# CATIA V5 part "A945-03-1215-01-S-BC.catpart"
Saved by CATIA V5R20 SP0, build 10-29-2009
Part number: A945-03-1215-01-S-BC
Source: Unknown
Property "ARTICLENO": "A945-03-1215-01-S-BC"
Property "B": "125.000"
Property "BOMINFO": "A945-03-1215-01-S-BC"
Property "CODE": "A945-03-1215-01-S-BC"
Property "D1": "26.000"
Property "D2": "17.500"
Property "D5": "20.000"
Property "D6": "16.000"
Property "H": "57.000"
Property "H1": "44.000"
Property "H2": "60.000"
Property "H3": "28.000"
Property "L1": "150.000"
Property "L2": "25.000"
Property "L3": "0.000"
Property "L4": "100.000"
Property "L5": "55.000"
Property "L6": "45.000"
Property "LINA": "A945-03-1215-01-S-BC"
Property "N": "5.000"
Property "NB": "A945-03-1215-01-S-BC"
Property "NBSYN": "$CODE."
Property "NN": "A945-03"
Property "NT": "v driver sets replaceable inserts pisitive return"
Property "SUPPLIER": "CF"
Property "Z": "85.000"
Bounding box of the stored display mesh (mm): x -669.473 to -511.473, y 748.188 to 833.188, z 0 to 150
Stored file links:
  C:\Users\Utente\Desktop\3D files A945-03\A945-03-1215-01-S-BC.catpart
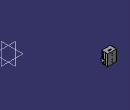
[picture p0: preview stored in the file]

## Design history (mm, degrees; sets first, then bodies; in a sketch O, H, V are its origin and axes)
Body1 "Geometry.1" (main body)
  Solid1 "A945-03-1215-01-S-BC.catpart": solid without history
